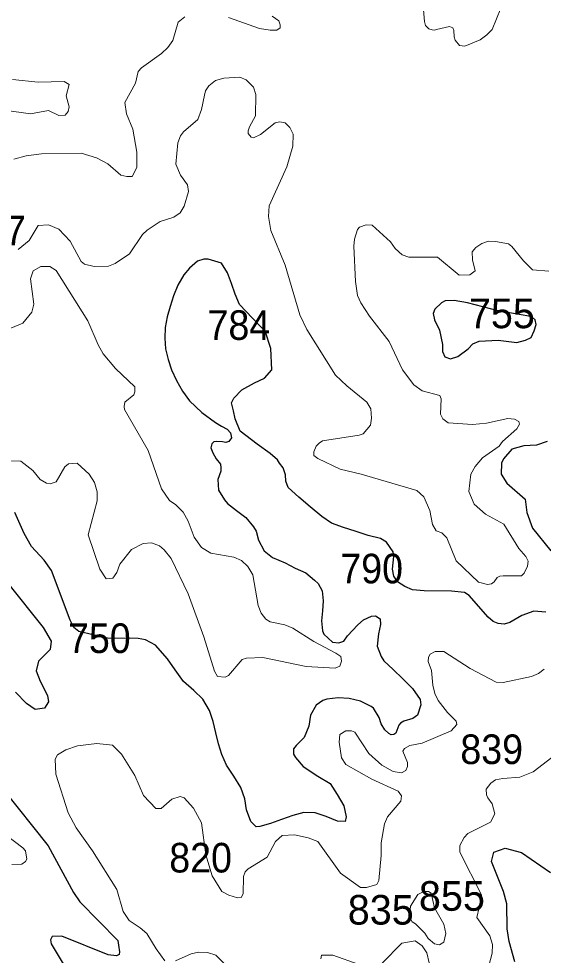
# Model space of a CAD drawing. Extents: x 499.9 to 555.3, y 9281.5 to 9336.8.
# Drawn here: x 542.72 to 545.56, y 9293.9 to 9298.96 of the extents above; entities that cross this region are included whole.
import ezdxf
from ezdxf.enums import TextEntityAlignment as Align

# ---------------------------------------------------------------- set-up
doc = ezdxf.new("R2010")
doc.units = 0
doc.header["$LTSCALE"] = 0.064
doc.layers.add('1', color=7, linetype='Continuous', lineweight=25)
doc.layers.add('2', color=7, linetype='Continuous', lineweight=13)
doc.layers.add('21', color=7, linetype='Continuous')
doc.layers.add('61', color=7, linetype='Continuous')

msp = doc.modelspace()

# ---------------------------------------------------------------- linework, layer by layer
at = {"layer": '1'}
for points in [[(544.1811, 9296.4274), (544.1694, 9296.4614), (544.1668, 9296.4958), (544.1546, 9296.534), (544.135, 9296.5595), (544.1238, 9296.577), (544.0841, 9296.6104), (544.014, 9296.6613), (543.9223, 9296.7319), (543.8952, 9296.798), (543.8862, 9296.8416), (543.8756, 9296.8841), (543.8883, 9296.9096), (543.9313, 9296.9542), (543.9997, 9296.9924), (544.0538, 9297.0178), (544.0929, 9297.0629), (544.0884, 9297.1787), (544.0568, 9297.2719), (544.0222, 9297.3065), (543.9185, 9297.4158), (543.8947, 9297.473), (543.8756, 9297.5303), (543.8533, 9297.5876), (543.8214, 9297.6401), (543.7483, 9297.6608), (543.7259, 9297.6608), (543.691, 9297.6497), (543.648, 9297.6131), (543.6177, 9297.5765), (543.5843, 9297.5208), (543.562, 9297.4635), (543.5429, 9297.4062), (543.527, 9297.3489), (543.5159, 9297.2916), (543.5143, 9297.2343), (543.5191, 9297.177), (543.5334, 9297.1197), (543.5509, 9297.0624), (543.578, 9297.0051), (543.6098, 9296.9478), (543.648, 9296.8953), (543.7148, 9296.8316), (543.788, 9296.7791), (543.8211, 9296.758), (543.8512, 9296.743), (543.8692, 9296.7219), (543.8752, 9296.6964), (543.8602, 9296.6753), (543.8451, 9296.6698), (543.8271, 9296.6738), (543.7955, 9296.6753), (543.7791, 9296.6735), (543.7689, 9296.6633), (543.7632, 9296.6417), (543.7734, 9296.6145), (543.7927, 9296.5827), (543.8151, 9296.5536), (543.8181, 9296.5325), (543.8183, 9296.5149), (543.8008, 9296.4704), (543.804, 9296.4131), (543.8374, 9296.3605), (543.8533, 9296.3398), (543.9026, 9296.3032), (543.9519, 9296.265), (543.9949, 9296.2141), (544.0092, 9296.1902), (544.022, 9296.1425), (544.0522, 9296.0852), (544.0968, 9296.0486), (544.1653, 9296.0199), (544.2194, 9295.9913), (544.2767, 9295.9658), (544.3244, 9295.926), (544.3435, 9295.9085), (544.3658, 9295.8688), (544.3706, 9295.8146), (544.3674, 9295.7605), (544.3626, 9295.7064), (544.3674, 9295.6523), (544.3753, 9295.6348), (544.4219, 9295.5913), (544.455, 9295.5867), (544.4821, 9295.5973), (544.5031, 9295.6258), (544.5584, 9295.6841), (544.5886, 9295.7111), (544.6322, 9295.7321), (544.6548, 9295.7336), (544.6788, 9295.7171), (544.6803, 9295.687), (544.6698, 9295.6359), (544.6634, 9295.5695), (544.6841, 9295.5138)], [(545.5824, 9296.6754), (545.5243, 9296.6567), (545.4567, 9296.6515), (545.3909, 9296.6339), (545.3463, 9296.5816), (545.3365, 9296.5585), (545.3339, 9296.4987), (545.3642, 9296.4509), (545.4633, 9296.364), (545.4722, 9296.2912), (545.5032, 9296.2072), (545.602, 9296.0844)], [(544.4804, 9296.2109), (544.4167, 9296.2348), (544.3642, 9296.2698), (544.3005, 9296.3223), (544.24, 9296.3749), (544.1811, 9296.4274)], [(543.4107, 9295.6045), (543.3707, 9295.6111), (543.2048, 9295.6126), (543.0503, 9295.6492), (543.0232, 9295.6695), (543.0029, 9295.7102), (542.9025, 9295.9776), (542.8616, 9296.0342), (542.7937, 9296.1078), (542.7531, 9296.1782), (542.704, 9296.292)], [(545.5761, 9295.7525), (545.5105, 9295.7586), (545.4456, 9295.7352), (545.3811, 9295.697), (545.3497, 9295.6887), (545.3175, 9295.6924), (545.2897, 9295.7032), (545.2628, 9295.7262), (545.1602, 9295.844), (545.1351, 9295.8591), (545.065, 9295.8668), (544.9181, 9295.8682), (544.8545, 9295.8732), (544.8135, 9295.8922), (544.7737, 9295.9168), (544.7528, 9295.9484), (544.7452, 9295.9851), (544.7528, 9296.0539), (544.7496, 9296.0788), (544.7135, 9296.1314), (544.6804, 9296.1509), (544.6142, 9296.1675), (544.544, 9296.1902), (544.4804, 9296.2109)], [(542.6643, 9295.9116), (542.8564, 9295.6704), (542.9002, 9295.5969), (542.8945, 9295.5515), (542.8318, 9295.4881), (542.8191, 9295.4365), (542.8405, 9295.3795), (542.8802, 9295.3029), (542.8852, 9295.2678), (542.8639, 9295.2336), (542.813, 9295.2273), (542.7671, 9295.2597), (542.707, 9295.3208)], [(544.8958, 9295.2815), (544.899, 9295.2528), (544.8814, 9295.1971), (544.856, 9295.178), (544.8082, 9295.1636), (544.7895, 9295.1536), (544.781, 9295.1421), (544.7634, 9295.099), (544.7531, 9295.0917), (544.7385, 9295.0905), (544.7264, 9295.0972), (544.7046, 9295.1167), (544.6851, 9295.1498), (544.6731, 9295.1843), (544.6427, 9295.2337), (544.63, 9295.2432), (544.5727, 9295.2719), (544.5122, 9295.2862), (544.4517, 9295.291), (544.3913, 9295.283), (544.3689, 9295.2751), (544.3339, 9295.2512), (544.3021, 9295.1971), (544.2926, 9295.1366), (544.2687, 9295.0762), (544.2257, 9295.0332), (544.2114, 9295.0141), (544.2114, 9294.9854), (544.2209, 9294.9679), (544.2623, 9294.9186), (544.3419, 9294.8661), (544.4087, 9294.8263), (544.4469, 9294.7674), (544.4835, 9294.7069), (544.4963, 9294.6464), (544.4899, 9294.6226), (544.4485, 9294.6241), (544.3881, 9294.648), (544.3276, 9294.6687), (544.2671, 9294.6703), (544.2066, 9294.6543), (544.1462, 9294.6321), (544.0857, 9294.6114), (544.0284, 9294.5939), (544.0093, 9294.5923), (543.979, 9294.6226), (543.9567, 9294.6846), (543.9472, 9294.7451), (543.9265, 9294.8056), (543.8883, 9294.8661), (543.8485, 9294.9265), (543.8231, 9294.9838), (543.804, 9295.0411), (543.7896, 9295.1016), (543.7753, 9295.1621), (543.7562, 9295.2226), (543.7196, 9295.2831), (543.6719, 9295.3292), (543.6161, 9295.3786), (543.57, 9295.4422), (543.5286, 9295.5011), (543.4634, 9295.5743), (543.4107, 9295.6045)], [(544.6841, 9295.5138), (544.7, 9295.4899), (544.7493, 9295.4438), (544.8018, 9295.3929), (544.8544, 9295.3403), (544.8958, 9295.2815)], [(542.6361, 9294.8009), (542.8839, 9294.4903), (543.0214, 9294.2375), (543.0547, 9294.1879), (543.2595, 9293.9787), (543.2641, 9293.9524), (543.2699, 9293.9173), (543.2668, 9293.9028), (543.2523, 9293.8961), (543.2083, 9293.9007), (542.9578, 9294.0025), (542.9046, 9294.0009), (542.8968, 9293.9819), (542.8991, 9293.9606), (542.987, 9293.8163)], [(545.4078, 9293.8635), (545.3766, 9293.9739), (545.3654, 9294.0407), (545.3647, 9294.1773), (545.3473, 9294.243), (545.2822, 9294.4057), (545.2946, 9294.4557), (545.3553, 9294.4778), (545.443, 9294.4543), (545.6004, 9294.346)]]:
    msp.add_lwpolyline(points, dxfattribs=at)
msp.add_lwpolyline([(545.155, 9297.176), (545.1812, 9297.2034), (545.2156, 9297.2175), (545.3184, 9297.2235), (545.4192, 9297.2111), (545.4653, 9297.2229), (545.4957, 9297.2387), (545.5131, 9297.2745), (545.5228, 9297.3081), (545.5171, 9297.3325), (545.5021, 9297.3476), (545.4836, 9297.3532), (545.3175, 9297.3816), (545.1516, 9297.4248), (545.0792, 9297.4371), (545.0312, 9297.4352), (545.0102, 9297.4255), (544.9757, 9297.3916), (544.9662, 9297.3674), (544.9738, 9297.3338), (545.0006, 9297.2771), (545.0164, 9297.2001), (545.0169, 9297.162), (545.0288, 9297.1325), (545.0604, 9297.1232), (545.0993, 9297.135)], close=True, dxfattribs=at)
at = {"layer": '2'}
for points in [[(544.9129, 9299.0087), (544.9192, 9298.9458), (544.9244, 9298.9249), (544.9421, 9298.9063), (544.9609, 9298.9013), (544.9738, 9298.8999), (544.9838, 9298.9023), (545.0546, 9298.9192), (545.0719, 9298.911), (545.0777, 9298.8971), (545.0796, 9298.8631), (545.0855, 9298.8449), (545.1092, 9298.8166), (545.1376, 9298.8132), (545.2194, 9298.8469), (545.2569, 9298.8736), (545.285, 9298.9032), (545.3556, 9299.0772)], [(543.3388, 9298.1085), (543.3628, 9298.1574), (543.363, 9298.2401), (543.3424, 9298.3635), (543.3077, 9298.4463), (543.2981, 9298.5081), (543.3561, 9298.6119), (543.3699, 9298.6751), (543.3892, 9298.6958), (543.4973, 9298.7728), (543.5306, 9298.8058), (543.5573, 9298.8441), (543.5873, 9298.9416), (543.6225, 9298.9704)], [(543.8596, 9298.9674), (544.0259, 9298.9084), (544.0842, 9298.8993), (544.1209, 9298.8991), (544.1377, 9298.9126), (544.1382, 9298.928), (544.1313, 9298.9497), (544.0958, 9298.9749)], [(542.6482, 9298.4676), (542.7882, 9298.4472), (542.8847, 9298.4643), (542.9411, 9298.438), (542.9761, 9298.4405), (542.9913, 9298.4597), (542.9965, 9298.4853), (542.9812, 9298.5434), (542.9965, 9298.6052), (542.9698, 9298.6212), (542.829, 9298.6188), (542.6914, 9298.6332)], [(545.0013, 9296.9244), (545.0101, 9296.9068), (545.0058, 9296.8239), (545.0188, 9296.7976), (545.047, 9296.777), (545.1782, 9296.768), (545.2538, 9296.7743), (545.3692, 9296.7996), (545.4058, 9296.7965), (545.4287, 9296.7845), (545.4326, 9296.7686), (545.4186, 9296.7436), (545.3419, 9296.6761), (545.3232, 9296.6513), (545.232, 9296.5868), (545.1927, 9296.54), (545.1689, 9296.499), (545.1584, 9296.4057), (545.1877, 9296.3376), (545.2482, 9296.2837), (545.3491, 9296.2281), (545.4286, 9296.0975), (545.4665, 9296.0541), (545.4795, 9296.0287), (545.4759, 9296.001), (545.4574, 9295.9642), (545.4436, 9295.9505), (545.3454, 9295.9496), (545.3269, 9295.9483), (545.312, 9295.9403), (545.2965, 9295.9167), (545.2815, 9295.9056), (545.2595, 9295.9026), (545.212, 9295.9145), (545.0897, 9296.0316), (545.0392, 9296.1544), (545.0123, 9296.1816), (544.983, 9296.1925), (544.9616, 9296.2274), (544.948, 9296.3024), (544.9157, 9296.3764), (544.8776, 9296.4106), (544.5766, 9296.4987), (544.4629, 9296.5254), (544.3427, 9296.5831), (544.3213, 9296.6), (544.3199, 9296.6199), (544.3332, 9296.6502), (544.3494, 9296.6671), (544.3674, 9296.6801), (544.5663, 9296.7101), (544.588, 9296.7179), (544.627, 9296.7649), (544.6329, 9296.8014), (544.6284, 9296.8524), (544.6069, 9296.889), (544.4982, 9296.976), (544.4384, 9297.0343), (544.2818, 9297.2816), (544.2454, 9297.3599), (544.1651, 9297.6289), (544.0874, 9297.816), (544.0746, 9297.8924), (544.0794, 9297.9504), (544.1745, 9298.1598), (544.2066, 9298.2727), (544.2095, 9298.3371), (544.1905, 9298.3738), (544.1655, 9298.3986), (544.1367, 9298.4045), (544.1106, 9298.3986), (544.0315, 9298.3357), (543.9941, 9298.317), (543.9813, 9298.3204), (543.9657, 9298.341), (543.9647, 9298.3556), (543.9725, 9298.3771), (544.0059, 9298.4353), (544.006, 9298.5512), (543.9942, 9298.5908), (543.9539, 9298.6311), (543.9204, 9298.6459), (543.8342, 9298.6395), (543.7885, 9298.6263), (543.7518, 9298.5987), (543.735, 9298.5707), (543.7287, 9298.5485), (543.7132, 9298.4701), (543.6938, 9298.4168), (543.6162, 9298.3498), (543.5991, 9298.3273), (543.5858, 9298.2902), (543.5734, 9298.1757), (543.6001, 9298.1158), (543.6365, 9298.0633)], [(542.6987, 9298.202), (542.7646, 9298.2194), (542.8473, 9298.2305), (543.0614, 9298.2351)], [(543.0614, 9298.2351), (543.1459, 9298.2085), (543.2058, 9298.177), (543.2771, 9298.1162), (543.3097, 9298.1081), (543.3388, 9298.1085)], [(543.6365, 9298.0633), (543.6428, 9298.0277), (543.619, 9297.9475), (543.5969, 9297.9124), (543.5634, 9297.8878), (543.4897, 9297.8641)], [(543.4897, 9297.8641), (543.4198, 9297.8178), (543.3945, 9297.7938), (543.3228, 9297.6893), (543.2468, 9297.637), (543.2102, 9297.6242), (543.1331, 9297.6211), (543.0801, 9297.6346), (543.0628, 9297.648), (543.0021, 9297.7587), (542.9409, 9297.8226), (542.8847, 9297.8468), (542.8301, 9297.8425), (542.7809, 9297.7617), (542.7208, 9297.7134)], [(545.5912, 9297.5957), (545.5031, 9297.6041), (545.454, 9297.6531), (545.3912, 9297.7302), (545.373, 9297.7434), (545.3023, 9297.7577), (545.2651, 9297.7578), (545.2301, 9297.7466), (545.1963, 9297.7239), (545.1778, 9297.7008), (545.1793, 9297.6569), (545.1923, 9297.5977), (545.1639, 9297.5764), (545.1073, 9297.5746), (544.9893, 9297.6716), (544.8344, 9297.6719), (544.7984, 9297.6855), (544.7611, 9297.719), (544.7359, 9297.7552), (544.6361, 9297.8452), (544.6037, 9297.8467), (544.5675, 9297.8336), (544.5566, 9297.8209), (544.541, 9297.7697), (544.5376, 9297.7316), (544.5455, 9297.5406), (544.5567, 9297.4643), (544.5746, 9297.4249), (544.6209, 9297.3535)], [(542.6823, 9297.2891), (542.7458, 9297.3149), (542.7946, 9297.3744), (542.8057, 9297.4175), (542.7876, 9297.5554), (542.8028, 9297.5974), (542.8436, 9297.6218), (542.8922, 9297.6217), (542.9261, 9297.6004), (543.0979, 9297.3282), (543.1533, 9297.1986), (543.1807, 9297.1496), (543.247, 9297.0703), (543.3528, 9296.9705), (543.3531, 9296.9447), (543.3465, 9296.9282), (543.2979, 9296.889), (543.2952, 9296.8657), (543.2962, 9296.8481), (543.425, 9296.6262), (543.4968, 9296.4194), (543.5402, 9296.357), (543.5746, 9296.3332), (543.6132, 9296.2929), (543.6411, 9296.245), (543.6731, 9296.1591), (543.7133, 9296.1027), (543.7642, 9296.0726), (543.8875, 9296.0503), (543.9301, 9296.032), (543.9634, 9296), (543.99, 9295.9546), (544.0191, 9295.7884), (544.0348, 9295.7478), (544.0613, 9295.7149), (544.085, 9295.7004), (544.1635, 9295.6845), (544.2065, 9295.6665), (544.3207, 9295.5951), (544.4391, 9295.5316), (544.4661, 9295.5131), (544.47, 9295.4888), (544.4608, 9295.462), (544.436, 9295.4498), (544.2799, 9295.4591), (544.045, 9295.5087), (543.957, 9295.5043), (543.9324, 9295.4971), (543.8595, 9295.4105), (543.8406, 9295.4024), (543.7998, 9295.4056), (543.7835, 9295.4351)], [(544.6209, 9297.3535), (544.7281, 9297.2158), (544.8, 9297.0631), (544.8611, 9296.9813), (544.9061, 9296.9492), (545.0013, 9296.9244)], [(543.4854, 9296.112), (543.4433, 9296.1277), (543.3973, 9296.1245), (543.335, 9296.0918), (543.2713, 9296.0126), (543.2546, 9295.9674), (543.2329, 9295.9379), (543.1967, 9295.9327), (543.1626, 9295.9864), (543.1007, 9296.1711), (543.1495, 9296.355), (543.1495, 9296.4042), (543.1349, 9296.4545), (543.1051, 9296.4989), (543.0407, 9296.5592), (542.994, 9296.5558), (542.9733, 9296.5383), (542.9277, 9296.458), (542.8937, 9296.4467), (542.8754, 9296.4501), (542.8401, 9296.47), (542.8009, 9296.5183), (542.7358, 9296.5686), (542.6819, 9296.572)], [(543.7835, 9295.4351), (543.7258, 9295.6204), (543.6402, 9295.852), (543.5491, 9296.0437), (543.5113, 9296.091), (543.4854, 9296.112)], [(543.515, 9293.8681), (543.4669, 9293.9327), (543.4165, 9294.0166), (543.3821, 9294.0478), (543.3222, 9294.0862), (543.2897, 9294.1349), (543.2546, 9294.2533), (543.1239, 9294.4623), (543.035, 9294.588), (542.9925, 9294.6683), (542.9251, 9294.8772), (542.9206, 9294.9587), (542.934, 9294.9823), (542.9795, 9295.0098), (543.0416, 9295.0315), (543.1466, 9295.0442), (543.2312, 9295.0351), (543.2805, 9294.9851), (543.353, 9294.8699), (543.3994, 9294.7616), (543.4657, 9294.6911), (543.4949, 9294.6912), (543.5524, 9294.7424), (543.5979, 9294.7575), (543.6193, 9294.7501), (543.6691, 9294.6939), (543.7128, 9294.6152), (543.7367, 9294.4411), (543.7708, 9294.3274), (543.8231, 9294.2438), (543.8605, 9294.2233), (543.9073, 9294.2088), (543.9278, 9294.2102), (543.9375, 9294.2301), (543.9404, 9294.3248), (543.9489, 9294.3502), (543.9658, 9294.3665), (544.0679, 9294.4285), (544.1138, 9294.5139), (544.1497, 9294.5469), (544.2168, 9294.549), (544.2901, 9294.533), (544.3427, 9294.5128), (544.4639, 9294.3429), (544.5721, 9294.2656), (544.6055, 9294.2653), (544.6608, 9294.282), (544.673, 9294.3028), (544.6855, 9294.4387), (544.6841, 9294.5063), (544.7028, 9294.6096), (544.7196, 9294.6468), (544.7917, 9294.7324), (544.7952, 9294.7602), (544.776, 9294.7859), (544.6336, 9294.8513), (544.4931, 9294.9298), (544.4708, 9294.9655), (544.4582, 9295.0506), (544.4613, 9295.0924), (544.4931, 9295.1125), (544.5248, 9295.1125), (544.5432, 9295.1049), (544.6176, 9294.9901), (544.6879, 9294.9261), (544.7502, 9294.8919), (544.7953, 9294.8839), (544.8174, 9294.8965), (544.8272, 9294.9199), (544.8271, 9294.9399), (544.8024, 9295.0015), (544.8116, 9295.0171), (544.84, 9295.0329), (544.9068, 9295.0443), (545.0633, 9295.1118), (545.0936, 9295.1452), (545.0902, 9295.1639), (545.0428, 9295.211), (544.9929, 9295.2766), (544.9753, 9295.3137), (544.9643, 9295.3594), (544.9578, 9295.4382), (544.9389, 9295.4872), (544.9401, 9295.5095), (544.9497, 9295.5271), (544.9769, 9295.5406), (545.023, 9295.5406)], [(545.023, 9295.5406), (545.1662, 9295.4495), (545.3072, 9295.3742), (545.3454, 9295.3722), (545.4982, 9295.4055), (545.5355, 9295.4215)], [(545.5355, 9295.4215), (545.5667, 9295.4452)], [(545.6077, 9294.9668), (545.5061, 9294.8895), (545.4352, 9294.8613), (545.3436, 9294.8548), (545.303, 9294.8472), (545.2771, 9294.8292), (545.2529, 9294.7965), (545.2544, 9294.7661), (545.2614, 9294.7495), (545.2855, 9294.7178), (545.3001, 9294.6626), (545.2753, 9294.619), (545.1531, 9294.5566), (545.1341, 9294.5358), (545.1106, 9294.4918), (545.1108, 9294.4554), (545.2267, 9294.2254), (545.2296, 9294.1881), (545.215, 9294.156), (545.203, 9294.1027), (545.2733, 9294.0033), (545.2861, 9293.9574), (545.286, 9293.9093), (545.2566, 9293.7996)], [(542.6485, 9294.5541), (542.7466, 9294.4797), (542.7601, 9294.463), (542.7675, 9294.418), (542.7617, 9294.4047), (542.7404, 9294.3909), (542.6879, 9294.3893)], [(544.9448, 9293.857), (544.9325, 9293.9117), (544.9058, 9293.95), (544.8683, 9293.9767), (544.7971, 9293.9649), (544.6901, 9293.8551)], [(543.8387, 9293.8505), (543.7904, 9293.8996), (543.7453, 9293.9145), (543.6973, 9293.9157), (543.6567, 9293.9064), (543.5731, 9293.8682)], [(544.5655, 9293.8492), (544.423, 9293.8997), (544.3623, 9293.9), (544.3583, 9293.8801)]]:
    msp.add_lwpolyline(points, dxfattribs=at)
msp.add_lwpolyline([(544.8701, 9294.0686), (544.9216, 9294.0186), (544.9398, 9293.9886), (544.9741, 9293.9613), (545.0009, 9293.9548), (545.0241, 9293.9691), (545.0337, 9294.0167), (545.0238, 9294.0666), (544.9732, 9294.1543), (544.9552, 9294.235), (544.9406, 9294.2427), (544.9152, 9294.2429), (544.8828, 9294.2266), (544.843, 9294.1648), (544.8372, 9294.1062), (544.8522, 9294.0792)], close=True, dxfattribs=at)

# ---------------------------------------------------------------- texts
at = {"layer": '21', "width": 0.95}
for s, p in [('717', (542.4238, 9297.7364)), ('784', (543.7455, 9297.225)), ('790', (544.4638, 9295.9091)), ('839', (545.1131, 9294.9322)), ('820', (543.5386, 9294.3461))]:
    msp.add_text(s, height=0.16, dxfattribs=at).set_placement(p)
at = {"layer": '21'}
for s, p in [('755', (545.1591, 9297.2882)), ('855', (544.889, 9294.1392)), ('835', (544.504, 9294.0645))]:
    msp.add_text(s, height=0.16, dxfattribs=at).set_placement(p)
at = {"layer": '61', "width": 0.95}
msp.add_text('750', height=0.16, dxfattribs=at).set_placement((543.1604, 9295.5326), align=Align.CENTER)

doc.saveas('drawing.dxf')
